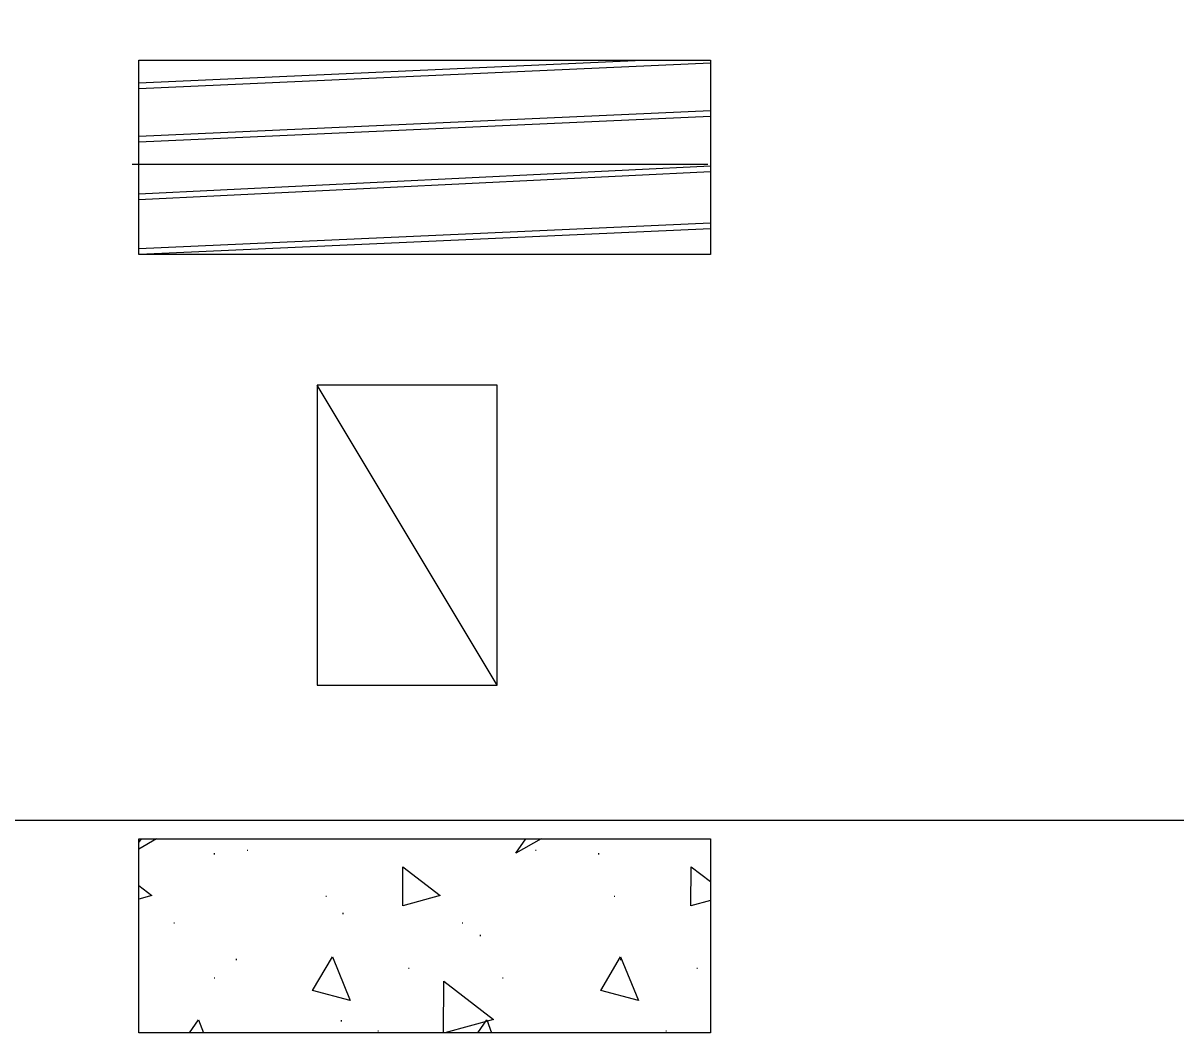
# Model space of a CAD drawing. Extents: x 6711682 to 6713077, y 1869209 to 1870525.
# Drawn here: x 6712178.5 to 6712265, y 1869948.8 to 1870024.5 of the extents above; entities that cross this region are included whole.
import ezdxf

# ---------------------------------------------------------------- set-up
doc = ezdxf.new("R2010")
doc.units = 0
for name, color, linetype in [('Control (1)', 7, 'Continuous'), ('G-TTLB-VIEW', 7, 'Continuous'), ('New Utility (40)', 7, 'Continuous'), ('Nongeo Data(60)', 7, 'Continuous')]:
    doc.layers.add(name, color=color, linetype=linetype)

msp = doc.modelspace()

# ---------------------------------------------------------------- linework, layer by layer
at = {"layer": 'Control (1)'}
for points in [[(6712187.207, 1870019.979), (6712224.973, 1870021.672)], [(6712230.061, 1870021.457), (6712187.207, 1870019.535)], [(6712187.207, 1870015.986), (6712230.061, 1870017.907)], [(6712230.061, 1870017.463), (6712187.207, 1870015.542)], [(6712187.207, 1870011.647), (6712230.061, 1870013.761)], [(6712230.061, 1870013.317), (6712187.207, 1870011.204)], [(6712187.207, 1870007.555), (6712230.061, 1870009.476)], [(6712230.061, 1870009.032), (6712187.264, 1870007.114)]]:
    msp.add_lwpolyline(points, dxfattribs=at)
at = {"layer": 'G-TTLB-VIEW'}
msp.add_lwpolyline([(6712030.317, 1870524.68), (6712727.825, 1870524.68), (6712727.825, 1869964.672), (6712030.317, 1869964.672)], close=True, dxfattribs=at)
at = {"layer": 'New Utility (40)'}
for p, q in [((6712214.065, 1869997.321), (6712200.57, 1869997.321)), ((6712200.57, 1869997.321), (6712200.57, 1869974.83)), ((6712214.065, 1869974.83), (6712200.57, 1869997.321)), ((6712214.065, 1869974.83), (6712214.065, 1869997.321)), ((6712200.57, 1869974.83), (6712214.065, 1869974.83)), ((6712214.065, 1869974.83), (6712214.065, 1869974.83))]:
    msp.add_line(p, q, dxfattribs=at)
at = {"layer": 'Nongeo Data(60)'}
msp.add_line((6712186.705, 1870013.873), (6712229.859, 1870013.873), dxfattribs=at)
for points in [[(6712187.207, 1870021.672), (6712230.061, 1870021.672), (6712230.061, 1870007.114), (6712187.207, 1870007.114)], [(6712187.207, 1869963.313), (6712230.061, 1869963.313), (6712230.061, 1869948.755), (6712187.207, 1869948.755)], [(6712206.988, 1869958.287), (6712207.011, 1869961.214), (6712209.8, 1869959.054)], [(6712200.233, 1869951.93), (6712201.716, 1869954.454), (6712203.051, 1869951.189)], [(6712221.849, 1869951.93), (6712223.332, 1869954.454), (6712224.668, 1869951.189)]]:
    msp.add_lwpolyline(points, close=True, dxfattribs=at)
for points in [[(6712187.207, 1869963.031), (6712187.4, 1869963.313)], [(6712188.538, 1869963.313), (6712187.207, 1869962.543)], [(6712217.359, 1869963.313), (6712215.48, 1869962.224), (6712216.222, 1869963.313)], [(6712230.061, 1869958.684), (6712228.604, 1869958.287), (6712228.627, 1869961.214), (6712230.061, 1869960.103)], [(6712187.207, 1869959.81), (6712188.184, 1869959.054), (6712187.207, 1869958.788)], [(6712210.036, 1869948.755), (6712210.066, 1869952.63), (6712213.785, 1869949.75), (6712210.138, 1869948.755)], [(6712191.003, 1869948.755), (6712191.68, 1869949.749), (6712192.041, 1869948.755)], [(6712212.619, 1869948.755), (6712213.296, 1869949.749), (6712213.658, 1869948.755)]]:
    msp.add_lwpolyline(points, dxfattribs=at)

# ---------------------------------------------------------------- texts
for height, p in [(0.8, (6712192.724, 1869962.125)), (0.6, (6712195.239, 1869962.389)), (0.6, (6712216.855, 1869962.389)), (0.8, (6712221.545, 1869962.125)), (0.6, (6712201.145, 1869958.942)), (0.6, (6712222.761, 1869958.942)), (0.8, (6712202.372, 1869957.652)), (0.6, (6712189.74, 1869956.958)), (0.6, (6712211.357, 1869956.958)), (0.8, (6712212.66, 1869955.991)), (0.8, (6712194.37, 1869954.196)), (0.8, (6712223.192, 1869954.196)), (0.6, (6712207.345, 1869953.558)), (0.6, (6712228.961, 1869953.558)), (0.6, (6712192.758, 1869952.831)), (0.6, (6712214.374, 1869952.831)), (0.8, (6712202.245, 1869949.601)), (0.6, (6712205.027, 1869948.853)), (0.6, (6712226.643, 1869948.853))]:
    msp.add_text('.', height=height, dxfattribs=at).set_placement(p)

doc.saveas('drawing.dxf')
